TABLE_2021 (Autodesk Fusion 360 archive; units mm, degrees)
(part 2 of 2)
sketch "Sketch2" plane through (0, 0, 0) normal (0, 1, 0) x axis (1, 0, 0)
  line L1 (0, -35) -> (55, -35)
  line L2 (0, 35) -> (0, -35)
  line L3 (55, 35) -> (0, 35)
  line L4 (55, -35) -> (55, 35)
  line L5 (0, 35) -> (55, -35)
  line L6 (55, 35) -> (0, -35)
  line L7 (38.5, 15) -> (38.5, -85)
  line L8 (28.5, -85) -> (28.5, 15)
  line L9 (33.5, 15) -> (33.5, -85)
  line L10 (38.5, 15) -> (33.5, 15)
  line L11 (0, 35) -> (0, -35)
  arc A1 centre (33.5, 15) radius 5 clockwise from (28.5, 15) to (38.5, 15)
  arc A2 centre (33.5, -85) radius 5 clockwise from (38.5, -85) to (28.5, -85)
  point P6 (27.5, 0)
  point P1 (0, 0)
  point P13 (33.5, -35)
  point P12 (33.5, 15)
  point P14 (33.5, 15)
  point P15 (38.5, 15)
  point P16 (38.5, 15)
  point P2 (55, -35)
  point P5 (55, 35)
  point P11 (33.5, -85)
  horizontal L1
  perpendicular L1 L2
  parallel L1 L3
  parallel L2 L4
  coincident L5 P6
  coincident L6 P6
  midpoint P1 L2
  tangent L7 A1
  tangent A1 L8
  parallel L7 L8
  tangent L8 A2
  tangent L7 A2
  coincident L1 P13
  midpoint L9 P13
  coincident P12 P14
  coincident A1 P15
  coincident P15 P16
  horizontal L10
  dimension "d21" distance P1 L4 = 55 (= "profondeurSupport - epMatiere")
  dimension "d22" distance P2 P5 = 70 (= "hauteurSupport")
  dimension "d23" radius A1 = 5 (= "( diaTourillon ) / 2")
  dimension "d25" angle L1 L7 = 90 (= "90 deg - angleInsert")
  dimension "d145" distance L3 P12 = 20
  dimension "d152" distance P11 L11 = 33.5
extrude "Extrude2" cut sketch "Sketch2" profile of L7 A1 L8 A2 distance 151.225
ground "Ground1"
ground "Ground2"
ground "Ground3"
sketch "Sketch4" plane through (0, 0, 0) normal (0, 1, 0) x axis (1, 0, 0)
  line L1 (22.5, 26) -> (44.5, 26)
  line L2 (22.5, -124) -> (22.5, 26)
  line L3 (44.5, -124) -> (22.5, -124)
  line L4 (44.5, 26) -> (44.5, -124)
  line L5 (22.5, -124) -> (44.5, 26)
  line L6 (44.5, -124) -> (22.5, 26)
  line L7 (33.5, -49) -> (33.5, 26)
  circle C1 centre (33.5, 15) radius 5
  arc A1 centre (33.5, 15) radius 5 clockwise from (28.5, 15) to (38.5, 15)
  point P10 (33.5, -49)
  point P11 (33.5, 26)
  point P12 (33.5, -49)
  point P2 (33.5, 15)
  point P6 (44.5, 26)
  point P7 (22.5, 26)
  point P9 (44.5, -124)
  concentric C1 A1
  horizontal L1
  perpendicular L1 L2
  parallel L1 L3
  parallel L2 L4
  coincident L5 P10
  coincident L6 P10
  midpoint L1 P11
  coincident P10 P12
  coincident P2 L7
  dimension "d32" diameter C1 = 10 (= "diaTourillon")
  dimension "d33" distance P2 L1 = 11 (= "epCarre / 2")
  dimension "d34" distance P6 P7 = 22 (= "epCarre")
  dimension "d35" distance P6 P9 = 150 (= "Linear Dimension-4")
extrude "Extrude1" new body sketch "Sketch4" profile of C1 L1 L2 L3 L4 no distance stored
extrude "Extrude2" sketch "Sketch4" profile of C1 blind 10 (= "longueurTourillon")
mirror "Mirror1"
chamfer "Chamfer1" distance 1
ground "Ground4"
ground "Ground5"
joint "Assemble1" alignAngle 0 alignOffsetX 0 alignOffsetY 0 alignOffsetZ 0
joint "Assemble2" alignAngle 0 alignOffsetX 0 alignOffsetY 0 alignOffsetZ 0
joint "Assemble3" alignAngle 0 alignOffsetX 0 alignOffsetY 0 alignOffsetZ 2.5 (= "jeuLateral / 2") AngleMinimum -180 AngleMaximum 23
ground "Ground7"
joint "Assemble4" alignAngle 180 alignOffsetX 0 alignOffsetY 0 alignOffsetZ 0
component_insert "Component Insert1"
position "Position1"
joint "Assemble5" OffsetX 0 OffsetY 0 OffsetZ 0 AngleZ 0 alignAngle 90 alignOffsetX 0 alignOffsetY 0 alignOffsetZ 0
component_insert "Component Insert2"
joint "Assemble6" OffsetX 0 OffsetY 0 OffsetZ 0 AngleZ 0 alignAngle 180 alignOffsetX 0 alignOffsetY 1 alignOffsetZ 0
component_insert "Component Insert3"
joint "Assemble7" OffsetX 0 OffsetY 0 OffsetZ 0 AngleZ 0 alignAngle 90 alignOffsetX 0 alignOffsetY 0 alignOffsetZ 0
component_insert "Component Insert4"
position "Position2"
joint "Assemble8" OffsetX 0 OffsetY 0 OffsetZ 0 AngleZ 0 alignAngle 180 alignOffsetX 0 alignOffsetY -1 alignOffsetZ 0
position "Position3"
sketch "Esquisse" plane through (0, 75, 0) normal (0, 1, 0) x axis (-1, 0, 0)
  line L1 (-44.5, -26) -> (-44.5, 124)
  line L2 (-22.5, -26) -> (-44.5, -26)
  line L3 (-22.5, 124) -> (-22.5, -26)
  line L4 (-44.5, 124) -> (-22.5, 124)
  arc A1 centre (-33.5, -15) radius 5 clockwise from (-28.8975, -13.0463) to (-38.1025, -16.9537)
  circle C1 centre (-33.5, -15) radius 1.5
  concentric A1 C1
  dimension "d146" diameter C1 = 3
extrude "Extrusion" cut sketch "Esquisse" profile of C1 against normal blind 150
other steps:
extrude "Extrude2" cut sketch "Sketch2" profile of L7 A1 L8 A2 distance 151.225
create_component "CreateComponent1"
create_component "CreateComponent2"
create_component "CreateComponent3"
create_component "CreateComponent4"
joint_origin "JointOrigin1" OffsetX 0 OffsetY 0 OffsetZ 0 AngleZ 0
joint_origin "JointOrigin1" OffsetX 0 OffsetY 0 OffsetZ 0 AngleZ 0
joint_origin "JointOrigin1" OffsetX 0 OffsetY 0 OffsetZ 0 AngleZ 0
joint_origin "JointOrigin2" OffsetX 0 OffsetY 0 OffsetZ 0 AngleZ 0
joint_origin "JointOrigin1" OffsetX 0 OffsetY 0 OffsetZ 0 AngleZ 0
joint_origin "JointOrigin2" OffsetX 0 OffsetY 0 OffsetZ 0 AngleZ 0
create_component "CreateComponent5"
joint_origin "JointOrigin3" OffsetX 0 OffsetY 0 OffsetZ 0 AngleZ 0
joint_origin "JointOrigin1" OffsetX 0 OffsetY 0 OffsetZ 0 AngleZ 0
joint_origin "JointOrigin2" OffsetX 0 OffsetY 0 OffsetZ 0 AngleZ 0
joint_origin "JointOrigin3" OffsetX 0 OffsetY 0 OffsetZ 0 AngleZ 0
joint_origin "JointOrigin2" OffsetX 0 OffsetY 0 OffsetZ 0 AngleZ 0
joint_origin "JointOrigin3" OffsetX 0 OffsetY 0 OffsetZ 0 AngleZ 0

design "MiddleBeaconVertSupport2"
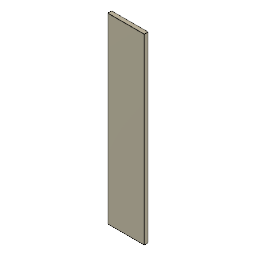
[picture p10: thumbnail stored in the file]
sketch "Sketch1"
  dimension "d1" = 1000
  dimension "d2" = 200
extrude "Extrude1" new body sketch "Sketch1" distance 22

design "BorderSmall"
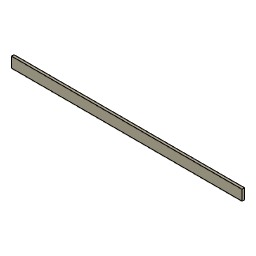
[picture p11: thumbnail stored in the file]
sketch "Sketch1" plane through (0, 0, 0) normal (0, 0, 1) x axis (1, 0, 0)
  line L1 (2044, 0) -> (0, 0)
  line L2 (2044, 92) -> (2044, 0)
  line L3 (0, 92) -> (2044, 92)
  line L4 (0, 0) -> (0, 92)
  point P1 (0, 0)
  point P2 (0, 0)
  point P3 (2044, 0)
  point P5 (0, 92)
  horizontal L1
  vertical L2
  horizontal L3
  vertical L4
  coincident P1 P2
  dimension "d1" distance P2 P3 = 2044 (= "2000 mm + 44 mm")
  dimension "d2" distance P2 P5 = 92 (= "70 mm + 22 mm")
  dimension "d6" distance = 600
  dimension "d7" distance = 422 (= "22 mm + 400 mm")
extrude "Extrude1" new body sketch "Sketch1" along normal blind 22

design "EdgeBeacons_Base"
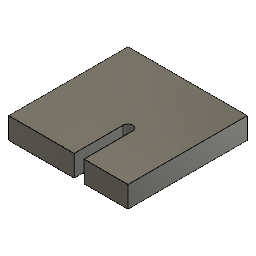
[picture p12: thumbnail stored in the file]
sketch "Sketch1" plane through (0, 0, 0) normal (0, 1, 0) x axis (1, 0, 0)
  line L1 (61, 61) -> (-61, 61)
  line L2 (61, -61) -> (61, 61)
  line L3 (-61, 61) -> (-61, -61)
  line L4 (61, -61) -> (-61, 61)
  line L5 (16, -11) -> (16, -61)
  line L6 (6, -61) -> (6, -11)
  line L7 (11, -11) -> (11, -61)
  line L8 (16, -61) -> (61, -61)
  line L9 (-61, -61) -> (6, -61)
  arc A1 centre (11, -11) radius 5 clockwise from (6, -11) to (16, -11)
  point P2 (-61, 61)
  point P3 (61, 61)
  point P10 (11, -61)
  point P11 (11, -11)
  dimension "d1" distance P2 P3 = 122
  dimension "d4" distance P10 P11 = 50
  dimension "d5" diameter A1 = 10
  dimension "d6" distance L2 L7 = 50
extrude "Extrude1" new body sketch "Sketch1" profile of L1 L2 L9 L3 along normal blind 22

design "CarreFouilleTresorJaune" references "CarreFouille"
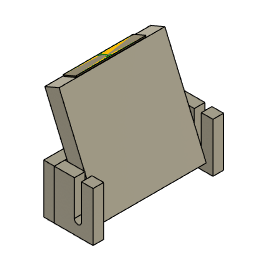
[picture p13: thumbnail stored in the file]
component_insert "Insertion d'un composant"
sketch "Esquisse1" plane through (64.4985, 0, 62.291) normal (0.9205, 0, 0.3907) x axis (0, 1, 0)
  line L1 (75, -52.2741) -> (-75, -52.2741)
  line L2 (75, 97.7259) -> (75, -52.2741)
  line L3 (-75, 97.7259) -> (75, 97.7259)
  line L4 (-75, -52.2741) -> (-75, 97.7259)
extrude "Extrusion1" new body sketch "Esquisse1" along a picked direction blind 0.01
sketch "Esquisse2" plane through (44.2474, 0, 53.695) normal (-0.9205, 0, -0.3907) x axis (0, -1, 0)
  line L1 (-75, 97.7259) -> (75, 97.7259)
  line L2 (-75, -52.2741) -> (-75, 97.7259)
  line L3 (75, -52.2741) -> (-75, -52.2741)
  line L4 (75, 97.7259) -> (75, -52.2741)
extrude "Extrusion2" new body sketch "Esquisse2" along a picked direction blind 0.01
decal "Décalcomanie"
joint "Assembler" alignAngle 0 alignOffsetX 0 alignOffsetY 0 alignOffsetZ 0
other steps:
joint_origin "JointOrigin1"

design "EchantillonVert"
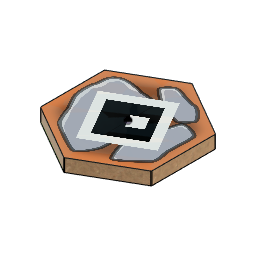
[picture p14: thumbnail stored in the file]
parameter "diaEchantillon" = 150
parameter "epEchantillon" = 15
sketch "Sketch1" plane through (0, 0, 0) normal (0, 0, 1) x axis (1, 0, 0)
  line L1 (0, 75) -> (64.9519, 37.5)
  line L2 (-64.9519, 37.5) -> (0, 75)
  line L3 (-64.9519, -37.5) -> (-64.9519, 37.5)
  line L4 (0, -75) -> (-64.9519, -37.5)
  line L5 (64.9519, -37.5) -> (0, -75)
  line L6 (64.9519, 37.5) -> (64.9519, -37.5)
  point P1 (0, 0)
  point P8 (0, 0)
  point P3 (0, 75)
  coincident P1 P8
  vertical L6
  dimension "d3" distance P3 P8 = 75 (= "diaEchantillon / 2")
extrude "Extrude1" new body sketch "Sketch1" along normal blind 15 (= "epEchantillon")
fillet "Congé" radius 1
decal "Décalcomanie1"
decal "Décalcomanie2"
sketch "Esquisse" plane through (0, 0, 15) normal (0, 0, 1) x axis (-1, 0, 0)
  line L1 (64.9519, 36.9226) -> (64.9519, -36.9226)
  line L2 (0.5, 74.7113) -> (64.4519, 37.7887)
  line L3 (-64.4519, 37.7887) -> (-0.5, 74.7113)
  line L4 (-64.9519, -36.9226) -> (-64.9519, 36.9226)
  line L5 (-0.5, -74.7113) -> (-64.4519, -37.7887)
  line L6 (64.4519, -37.7887) -> (0.5, -74.7113)
  arc A1 centre (63.9519, -36.9226) radius 1 clockwise from (64.9519, -36.9226) to (64.4519, -37.7887)
  arc A2 centre (63.9519, 36.9226) radius 1 clockwise from (64.4519, 37.7887) to (64.9519, 36.9226)
  arc A3 centre (0, 73.8453) radius 1 clockwise from (-0.5, 74.7113) to (0.5, 74.7113)
  arc A4 centre (-63.9519, 36.9226) radius 1 clockwise from (-64.9519, 36.9226) to (-64.4519, 37.7887)
  arc A5 centre (-63.9519, -36.9226) radius 1 clockwise from (-64.4519, -37.7887) to (-64.9519, -36.9226)
  arc A6 centre (0, -73.8453) radius 1 clockwise from (0.5, -74.7113) to (-0.5, -74.7113)
  point P1 (0, 0)
  point P20 (0, 0)
  coincident P1 P20

design "SupportCarreFouille"
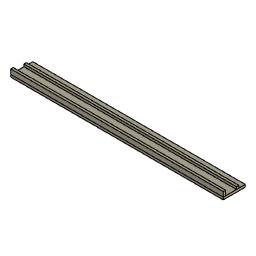
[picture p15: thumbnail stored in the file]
sketch "Esquisse" plane through (0, 0, 0) normal (1, 0, 0) x axis (0, 1, 0)
  line L1 (202, 0) -> (0, 0)
  line L2 (202, 22) -> (202, 0)
  line L3 (0, 22) -> (202, 22)
  line L4 (0, 0) -> (0, 22)
  line L5 (0, 66) -> (0, 22)
  line L6 (22, 66) -> (0, 66)
  line L7 (22, 22) -> (22, 66)
  line L8 (121, 44) -> (121, 22)
  line L9 (143, 44) -> (121, 44)
  line L10 (143, 22) -> (143, 44)
  point P1 (0, 0)
  point P2 (0, 0)
  point P6 (0, 0)
  point P9 (22, 22)
  point P10 (121, 22)
  point P13 (143, 22)
  point P7 (0, 66)
  point P8 (22, 66)
  point P5 (0, 22)
  point P11 (121, 44)
  point P12 (143, 44)
  coincident P1 P2
  horizontal L1
  perpendicular L1 L2
  perpendicular L2 L3
  coincident P1 P6
  perpendicular L1 L4
  perpendicular L3 L5
  perpendicular L4 L6
  coincident L3 P9
  perpendicular L3 L7
  coincident L3 P10
  perpendicular L3 L8
  perpendicular L8 L9
  coincident L3 P13
  perpendicular L3 L10
  dimension "d1" distance L1 L3 = 22
  dimension "d3" distance P7 P8 = 22
  dimension "d4" distance P5 P7 = 44
  dimension "d5" distance P11 P12 = 22
  dimension "d6" distance P10 P11 = 22
  dimension "d8" distance L2 L10 = 59
  dimension "d9" distance L2 L7 = 180
extrude "Extrusion1" new body sketch "Esquisse" profile of L1 L2 L3 L4 distance 975 (= "( 1950 / 2 ) * 1 mm")
extrude "Extrusion2" new body sketch "Esquisse" profile of L3 L5 L6 L7 distance 975 (= "( 1950 / 2 ) * 1 mm")
extrude "Extrusion3" new body sketch "Esquisse" profile of L3 L8 L9 L10 distance 975 (= "( 1950 / 2 ) * 1 mm")

design "EdgeBeacons_SmallBorder"
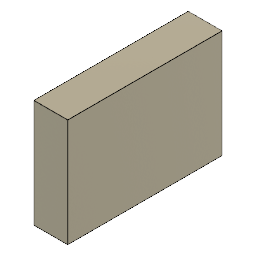
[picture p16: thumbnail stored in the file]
sketch "Sketch1" plane through (0, 0, 0) normal (1, 0, 0) x axis (0, 0, -1)
  line L1 (100, 70) -> (0, 70)
  line L2 (100, 0) -> (100, 70)
  line L3 (0, 0) -> (100, 0)
  line L4 (0, 70) -> (0, 0)
  point P1 (0, 0)
  point P5 (0, 0)
  point P2 (0, 70)
  point P3 (100, 70)
  horizontal L1
  vertical L2
  horizontal L3
  vertical L4
  coincident P1 P5
  dimension "d1" distance P2 P5 = 70 (= "48 mm + 22 mm")
  dimension "d2" distance P2 P3 = 100 (= "122 mm - 22 mm")
extrude "Extrude1" new body sketch "Sketch1" along normal blind 22

design "PaintExperience"
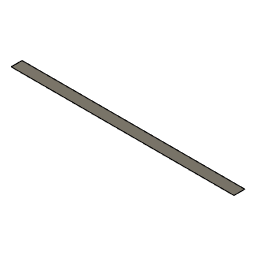
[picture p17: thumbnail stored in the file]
sketch "Sketch1" plane through (0, 0, 0) normal (0, 1, 0) x axis (1, 0, 0)
  line L1 (450, 0) -> (0, 0)
  line L2 (0, 0) -> (450, -22)
  line L3 (0, 0) -> (0, -22)
  line L4 (0, 0) -> (0, 0)
  point P1 (0, 0)
  point P2 (0, 0)
  point P3 (450, 0)
  point P5 (0, -22)
  horizontal L1
  vertical L2
  horizontal L3
  vertical L4
  coincident P1 P2
  dimension "d1" distance P2 P3 = 450
  dimension "d2" distance P2 P5 = 22
extrude "Extrude1" new body sketch "Sketch1" along normal blind 0.1

design "CarreFouilleTresorViolet" references "CarreFouille"
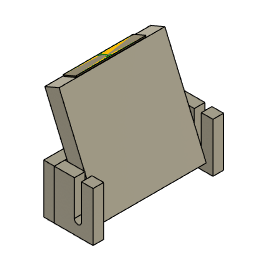
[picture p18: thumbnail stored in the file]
component_insert "Insertion d'un composant"
sketch "Esquisse1" plane through (64.4985, 0, 62.291) normal (0.9205, 0, 0.3907) x axis (0, 1, 0)
  line L1 (75, -52.2741) -> (-75, -52.2741)
  line L2 (75, 97.7259) -> (75, -52.2741)
  line L3 (-75, 97.7259) -> (75, 97.7259)
  line L4 (-75, -52.2741) -> (-75, 97.7259)
extrude "Extrusion1" new body sketch "Esquisse1" along a picked direction blind 0.01
sketch "Esquisse2" plane through (44.2474, 0, 53.695) normal (-0.9205, 0, -0.3907) x axis (0, -1, 0)
  line L1 (-75, 97.7259) -> (75, 97.7259)
  line L2 (-75, -52.2741) -> (-75, 97.7259)
  line L3 (75, -52.2741) -> (-75, -52.2741)
  line L4 (75, 97.7259) -> (75, -52.2741)
extrude "Extrusion2" new body sketch "Esquisse2" along a picked direction blind 0.01
decal "Décalcomanie"
joint "Assembler" alignAngle 0 alignOffsetX 0 alignOffsetY 0 alignOffsetZ 0
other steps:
joint_origin "JointOrigin1"

design "FriseJaune" references "Frise"
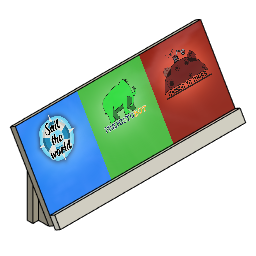
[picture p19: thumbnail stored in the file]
component_insert "Insertion d'un composant"
sketch "Esquisse" plane through (49.3634, 0, 28.5) normal (0.866, 0, 0.5) x axis (0, 1, 0)
  line L1 (360, -20.2073) -> (-360, -20.2073)
  line L2 (360, 279.7927) -> (360, -20.2073)
  line L3 (-360, 279.7927) -> (360, 279.7927)
  line L4 (-360, -20.2073) -> (-360, 279.7927)
extrude "Extrusion" new body sketch "Esquisse" along normal blind 0.01
decal "Décalcomanie"
joint "Assembler" alignAngle -90 alignOffsetX 0 alignOffsetY 0 alignOffsetZ 0
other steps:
joint_origin "JointOrigin1"

design "MiddleBeaconVertSupport1"
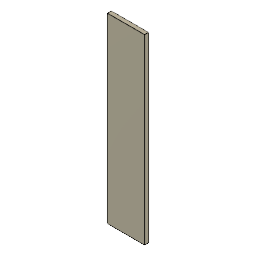
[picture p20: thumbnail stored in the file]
sketch "Sketch1"
  dimension "d1" = 978 (= "1000 mm - 22 mm")
  dimension "d2" = 200
extrude "Extrude1" new body sketch "Sketch1" distance 22

design "PCB_datation"
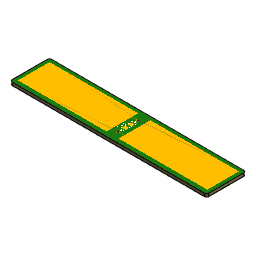
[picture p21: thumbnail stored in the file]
part number: CONTACT_CDR
pcb "PCB1" sketch "Sketch1" + "Sketch1" BoardHeight 1.57
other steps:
extrude "Extrude1" new body sketch "Sketch1" along normal blind 0.1 bodies "0207/10"
extrude "Extrude1" new body sketch "Sketch1" along normal blind 0.1 bodies "R1206"
base_feature "Base Feature1" sketch "Sketch1"
base_feature "Base Feature1" sketch "Sketch1"
extrude "Extrude1" new body sketch "Sketch1" along normal blind 1.57 bodies "Board"
extrude "Extrude4" sketch "Sketch4" blind 1.57
create_component "CreateComponent1"
create_component "CreateComponent1"
sketch "Sketch1" plane through (0, 0, 0) normal (0, 0, 1) x axis (1, 0, 0)
  line L1 (-49, 10) -> (49, 10)
  line L2 (-50, -9) -> (-50, 9)
  line L3 (49, -10) -> (-49, -10)
  line L4 (50, 9) -> (50, -9)
  arc A1 centre (49, 9) radius 1 clockwise from (49, 10) to (50, 9)
  arc A2 centre (-49, 9) radius 1 clockwise from (-50, 9) to (-49, 10)
  arc A3 centre (-49, -9) radius 1 clockwise from (-49, -10) to (-50, -9)
  arc A4 centre (49, -9) radius 1 clockwise from (50, -9) to (49, -10)
  point P4 (-50, 10)
  point P2 (-50, -10)
  point P3 (50, 10)
  vertical L2
  horizontal L1
  coincident P4 L1
  coincident P4 L2
  coincident P2 L2
  coincident P3 L1
  dimension "d14" distance P3 P4 = 100
  dimension "d15" distance P2 P4 = 20
  dimension "d19" radius = 1
create_component "CreateComponent2" sketch "Sketch1"
sketch "Sketch1" plane through (0, 0, 0) normal (0, 0, 1) x axis (1, 0, 0)
  line L1 (5.4865, -1.143) -> (-5.4865, -1.143)
  line L2 (5.4865, 1.143) -> (5.4865, -1.143)
  line L3 (-5.4865, 1.143) -> (5.4865, 1.143)
  line L4 (-5.4865, -1.143) -> (-5.4865, 1.143)
create_component "CreateComponent3" sketch "Sketch1"
sketch "Sketch1" plane through (0, 0, 0) normal (0, 0, 1) x axis (1, 0, 0)
  line L1 (1.689, -0.876) -> (-1.689, -0.876)
  line L2 (1.689, 0.876) -> (1.689, -0.876)
  line L3 (-1.689, 0.876) -> (1.689, 0.876)
  line L4 (-1.689, -0.876) -> (-1.689, 0.876)
canvas "Canvas5"
canvas "Canvas6"
sketch "Sketch4" plane through (0, 0, 0) normal (0, 0, 1) x axis (1, 0, 0)
  circle C1 centre (0, -4.953) radius 0.4065
  circle C2 centre (0, 5.207) radius 0.4065
create_component "CreateComponent6"
as_built_joint "As-built3"
named bodies: "Board", "0207/10", "R1206"

design "EdgeBeacons_LargeBorder"
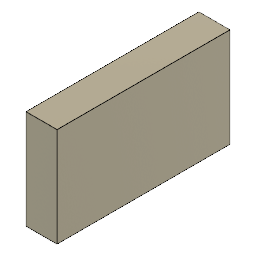
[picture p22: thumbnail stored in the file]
sketch "Sketch1" plane through (0, 0, 0) normal (1, 0, 0) x axis (0, 0, -1)
  line L1 (122, 70) -> (0, 70)
  line L2 (122, 0) -> (122, 70)
  line L3 (0, 0) -> (122, 0)
  line L4 (0, 70) -> (0, 0)
  point P1 (0, 0)
  point P5 (0, 0)
  point P2 (0, 70)
  point P3 (122, 70)
  horizontal L1
  vertical L2
  horizontal L3
  vertical L4
  coincident P1 P5
  dimension "d1" distance P2 P5 = 70 (= "48 mm + 22 mm")
  dimension "d2" distance P2 P3 = 122
extrude "Extrude1" new body sketch "Sketch1" along normal blind 22

design "Distributeur 2 Top" references "EchantillonRouge", "EchantillonVert", "EchantillonBleu"
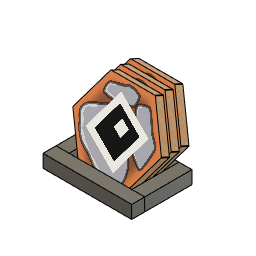
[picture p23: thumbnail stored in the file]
sketch "Esquisse1" plane through (0, 0, 0) normal (0, 1, 0) x axis (1, 0, 0)
  line L1 (-53, 11) -> (53, 11)
  line L2 (-53, -11) -> (-53, 11)
  line L3 (53, -11) -> (-53, -11)
  line L4 (53, 11) -> (53, -11)
  line L5 (-53, -11) -> (53, 11)
  line L6 (53, -11) -> (-53, 11)
  point P6 (0, 0)
  point P1 (0, 0)
  point P4 (-53, -11)
  point P5 (53, -11)
  point P3 (-53, 11)
  horizontal L1
  perpendicular L1 L2
  parallel L1 L3
  parallel L2 L4
  coincident L5 P6
  coincident L6 P6
  coincident P1 P6
  dimension "d1" distance P4 P5 = 106
  dimension "d2" distance P3 P4 = 22
  dimension "d105" OffsetX = 0
  dimension "d106" OffsetY = 0
  dimension "d107" OffsetZ = 0
  dimension "d108" AngleZ = 0
extrude "Extrusion1" new body sketch "Esquisse1" profile of L1 L2 L3 L4 along normal blind 22
sketch "Esquisse1" plane through (0, 0, 0) normal (0, 1, 0) x axis (1, 0, 0)
  line L1 (-11, -40) -> (11, -40)
  line L2 (-11, 40) -> (-11, -40)
  line L3 (11, 40) -> (-11, 40)
  line L4 (11, -40) -> (11, 40)
  line L5 (-11, 40) -> (11, -40)
  line L6 (11, 40) -> (-11, -40)
  point P6 (0, 0)
  point P1 (0, 0)
  point P4 (-11, 40)
  point P5 (11, 40)
  point P3 (-11, -40)
  horizontal L1
  perpendicular L1 L2
  parallel L1 L3
  parallel L2 L4
  coincident L5 P6
  coincident L6 P6
  coincident P1 P6
  dimension "d5" distance P4 P5 = 22
  dimension "d6" distance P3 P4 = 80
extrude "Extrusion1" new body sketch "Esquisse1" profile of L1 L2 L3 L4 along normal blind 22
copy_paste "CopyPaste1"
joint "Assembler1" alignAngle 0 alignOffsetX 0 alignOffsetY 0 alignOffsetZ 0
joint "Assembler2" alignAngle 0 alignOffsetX 0 alignOffsetY 0 alignOffsetZ 0
sketch "Esquisse1" plane through (0, 0, 0) normal (0, 1, 0) x axis (1, 0, 0)
  line L1 (-75, -11) -> (75, -11)
  line L2 (-75, 11) -> (-75, -11)
  line L3 (75, 11) -> (-75, 11)
  line L4 (75, -11) -> (75, 11)
  line L5 (-75, 11) -> (75, -11)
  line L6 (75, 11) -> (-75, -11)
  point P6 (0, 0)
  point P1 (0, 0)
  point P4 (-75, 11)
  point P5 (75, 11)
  point P3 (-75, -11)
  horizontal L1
  perpendicular L1 L2
  parallel L1 L3
  parallel L2 L4
  coincident L5 P6
  coincident L6 P6
  coincident P1 P6
  dimension "d33" distance P4 P5 = 150
  dimension "d34" distance P3 P4 = 22
extrude "Extrusion1" new body sketch "Esquisse1" profile of L1 L2 L3 L4 along normal blind 22
joint "Assembler3" alignAngle 180 alignOffsetX 0 alignOffsetY 0 alignOffsetZ 0
sketch "Esquisse1" plane through (0, 0, 0) normal (0, 1, 0) x axis (1, 0, 0)
  line L1 (100, 50) -> (-100, 50)
  line L2 (100, 28) -> (100, 50)
  line L3 (-100, 28) -> (100, 28)
  line L4 (-100, 50) -> (-100, 28)
  point P2 (-100, 50)
  point P3 (100, 50)
  point P5 (-100, 28)
  horizontal L1
  vertical L2
  horizontal L3
  vertical L4
  dimension "d49" distance P2 P3 = 200
  dimension "d50" distance P2 P5 = 22
extrude "Extrusion1" new body sketch "Esquisse1" along normal blind 70
joint "Assembler4" alignAngle 0 alignOffsetX 0 alignOffsetY 0 alignOffsetZ 0
component_insert "Component Insert"
ground "Ground1"
ground "Ground2"
work_plane "WorkPlane1"
component_insert "Insertion d'un composant9"
joint "Assembler23" alignAngle 90 alignOffsetX 0 alignOffsetY 0 alignOffsetZ 0
sketch "Sketch3" plane through (-53, 22, 11) normal (0, 0.4167, 0.9091) x axis (-1, 0, 0)
  point P1 (0, 0)
  point P2 (0, 0)
  coincident P1 P2
joint "Assembler24" alignAngle 0 alignOffsetX 0 alignOffsetY 0 alignOffsetZ 0
component_insert "Insertion d'un composant10"
joint "Assembler25" alignAngle 0 alignOffsetX 0 alignOffsetY 0 alignOffsetZ 0
joint "Assembler26" alignAngle 90 alignOffsetX 0 alignOffsetY 0 alignOffsetZ 0
joint "Assembler27" alignAngle 0 alignOffsetX 0 alignOffsetY 0 alignOffsetZ 0
joint "Assembler28" alignAngle 90 alignOffsetX 0 alignOffsetY 0 alignOffsetZ 0
joint "Assemble12" OffsetX 0 OffsetY 0 OffsetZ 0 AngleZ 0 alignAngle 0 alignOffsetX 0 alignOffsetY 0 alignOffsetZ 0
component_insert "Insertion d'un composant7"
joint "Assembler18" alignAngle 0 alignOffsetX 0 alignOffsetY 0 alignOffsetZ 0
joint "Assembler20" alignAngle 90 alignOffsetX 0 alignOffsetY 0 alignOffsetZ 0
component_insert "Insertion d'un composant8"
joint "Assembler21" alignAngle 0 alignOffsetX 0 alignOffsetY 0 alignOffsetZ 0
joint "Assembler22" alignAngle 90 alignOffsetX 0 alignOffsetY 0 alignOffsetZ 0
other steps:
create_component "CreateComponent1"
create_component "CreateComponent2"
joint_origin "JointOrigin1" OffsetX 0 OffsetY 0 OffsetZ 0 AngleZ 0
joint_origin "JointOrigin1" OffsetX 0 OffsetY 0 OffsetZ 0 AngleZ 0
joint_origin "JointOrigin2" OffsetX 0 OffsetY 0 OffsetZ 0 AngleZ 0
joint_origin "JointOrigin2" OffsetX 0 OffsetY 0 OffsetZ 0 AngleZ 0
create_component "CreateComponent3"
joint_origin "JointOrigin1" OffsetX 0 OffsetY 0 OffsetZ 0 AngleZ 0
joint_origin "JointOrigin3" OffsetX 0 OffsetY 0 OffsetZ 0 AngleZ 0
create_component "CreateComponent4"
joint_origin "JointOrigin1" OffsetX 0 OffsetY 0 OffsetZ 0 AngleZ 0
joint_origin "JointOrigin3" OffsetX 0 OffsetY 0 OffsetZ 0 AngleZ 0
joint_origin "JointOrigin2" OffsetX 0 OffsetY 0 OffsetZ 0 AngleZ 0
joint_origin "JointOrigin10"
joint_origin "JointOrigin11"
joint_origin "JointOrigin12"
joint_origin "JointOrigin4"
joint_origin "JointOrigin13"
joint_origin "JointOrigin2"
